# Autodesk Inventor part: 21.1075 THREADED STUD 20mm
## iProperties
Created: 2007-03
Part Number: 21.1075 THREADED STUD 20mm
Document SubType Name: Modeling
Designer: Andy Moles
Material: Steel
Mass: 459.387 g
Surface Area: 125.618 cm^2
Volume: 58.5207 cm^3
Density: 7.85 g/cm^3
Author: Andy Moles
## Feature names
1. Revolution1
2. Extrusion1
3. Extrusion2
4. Extrusion3
5. Chamfer1
